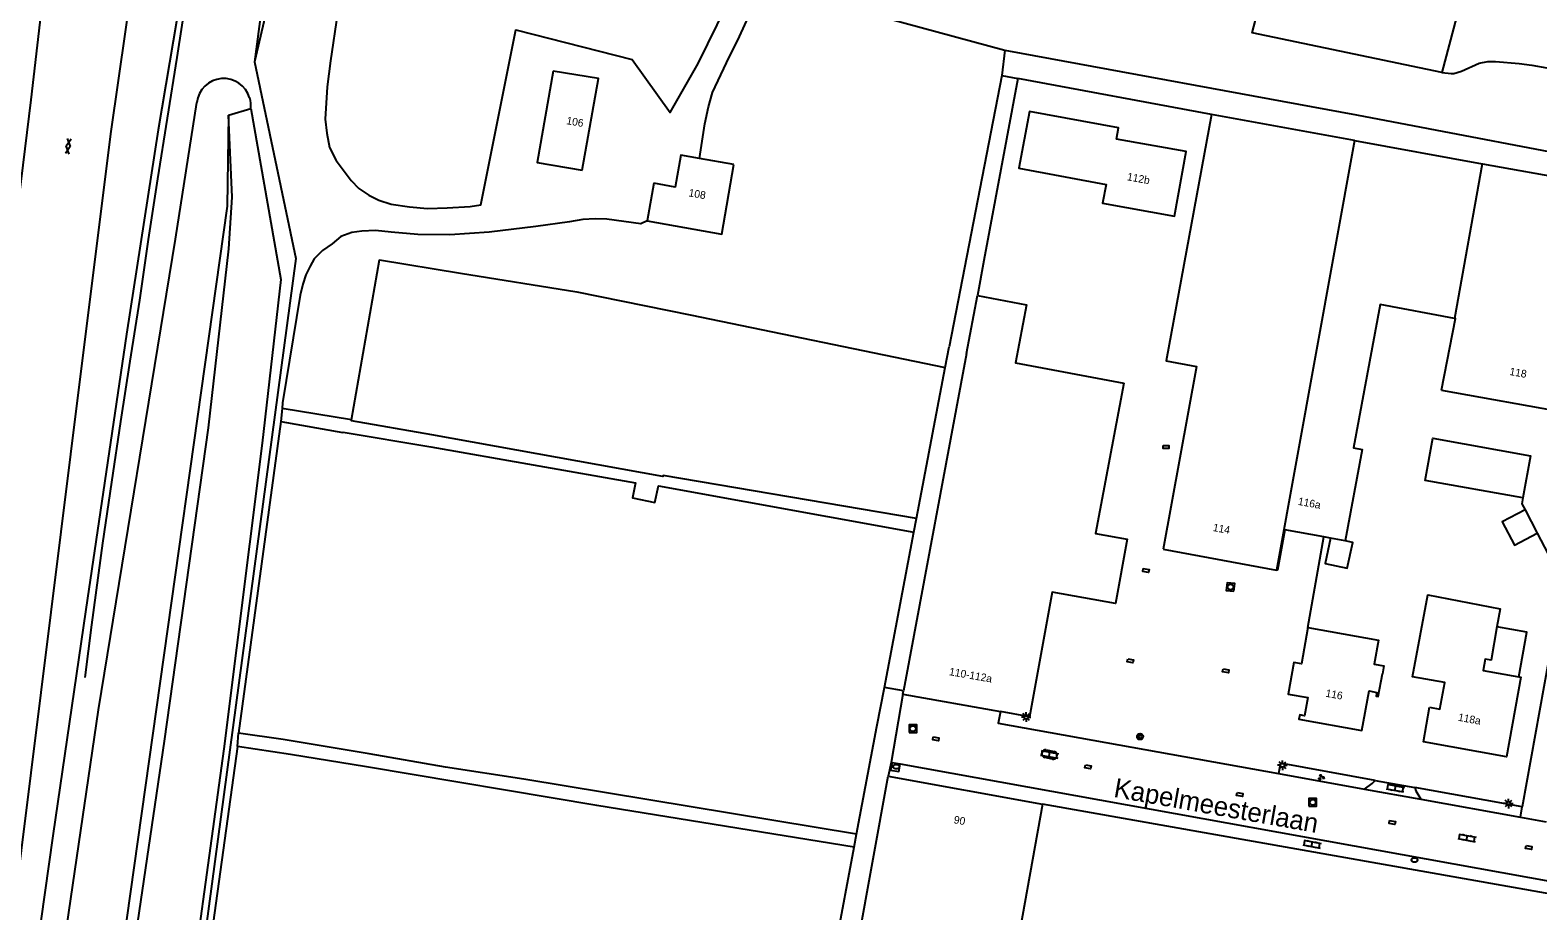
# Model space of a CAD drawing. Extents: x 133000 to 136000, y 400500 to 403500.
# Drawn here: x 133102.6 to 133299.1, y 400603.1 to 400718 of the extents above; entities that cross this region are included whole.
import ezdxf

# ---------------------------------------------------------------- set-up
doc = ezdxf.new("R2010")
doc.units = 0
for name, color, linetype in [('gg-afsc-hekwerk', 7, 'Continuous'), ('gg-afsc-muur', 7, 'Continuous'), ('gg-anno-huisnummerreeks BGT', 7, 'Continuous'), ('gg-anno-openbare ruimte label', 7, 'Continuous'), ('gg-bbg-bijgebouw', 7, 'Continuous'), ('gg-bbg-gedigitaliseerde bebouwing', 7, 'Continuous'), ('gg-bbg-hoofdgebouw', 7, 'Continuous'), ('gg-bbg-luifel en loopbrug', 7, 'Continuous'), ('gg-bbg-tussenscheiding', 7, 'Continuous'), ('gg-knt-BGT kruinlijn', 7, 'Continuous'), ('gg-knt-bovenkant onderkant talud', 7, 'Continuous'), ('gg-knt-verharding', 7, 'Continuous'), ('gt-grn-groengrens', 7, 'Continuous'), ('gt-grn-weggrens', 7, 'Continuous'), ('gt-knt-geleideconstructie', 7, 'Continuous'), ('gt-symb-boom', 7, 'Continuous'), ('gt-symb-brandkraan', 7, 'Continuous'), ('gt-symb-gesloten verharding', 7, 'Continuous'), ('gt-symb-groenvak', 7, 'Continuous'), ('gt-symb-klinker verharding', 7, 'Continuous'), ('gt-symb-kolk center center', 7, 'Continuous'), ('gt-symb-lichtmast', 7, 'Continuous'), ('gt-symb-rioolschacht', 7, 'Continuous')]:
    doc.layers.add(name, color=color, linetype=linetype)

# ---------------------------------------------------------------- blocks, each defined once
blk = doc.blocks.new('gt0-KL1')
at = {"layer": 'gt-symb-klinker verharding'}
for p, q in [((-1.15, 0.3), (1.15, 0.3)), ((-1, -0.3), (-1, 0.3)), ((-0.5, 0.3), (-0.5, 0.45)), ((0, -0.3), (0, 0.3)), ((0.5, 0.3), (0.5, 0.45)), ((1, -0.3), (1, 0.3)), ((-1.15, -0.3), (1.15, -0.3)), ((-0.5, -0.45), (-0.5, -0.3)), ((0.5, -0.45), (0.5, -0.3))]:
    blk.add_line(p, q, dxfattribs=at)
blk = doc.blocks.new('gt0-KOLKCC')
at = {"layer": 'gt-symb-kolk center center'}
blk.add_lwpolyline([(-0.38, 0.2), (0.38, 0.2), (0.38, -0.2), (-0.38, -0.2)], close=True, dxfattribs=at)
blk = doc.blocks.new('gt0-BOOM')
at = {"layer": 'gt-symb-boom'}
for radius in [0.4, 0.2]:
    blk.add_circle((0, 0), radius, dxfattribs=at)
blk = doc.blocks.new('gt0-RS')
at = {"layer": 'gt-symb-rioolschacht'}
blk.add_lwpolyline([(-0.5, -0.5), (0.5, -0.5), (0.5, 0.5), (-0.5, 0.5)], close=True, dxfattribs=at)
blk.add_circle((0, 0), 0.375, dxfattribs=at)
blk = doc.blocks.new('gt0-LMAST')
at = {"layer": 'gt-symb-lichtmast'}
for p, q in [((-0.18, 0.17), (-0.45, 0.44)), ((-0.01, 0.25), (-0.01, 0.62)), ((0.17, 0.17), (0.44, 0.44)), ((-0.26, 0), (-0.63, 0)), ((-0.18, -0.18), (-0.45, -0.45)), ((-0.01, -0.25), (-0.01, -0.63)), ((0.44, -0.45), (0.17, -0.18)), ((0.24, 0), (0.62, 0))]:
    blk.add_line(p, q, dxfattribs=at)
blk.add_circle((-0.01, 0), 0.25, dxfattribs=at)
blk = doc.blocks.new('gt0-GRVAK')
at = {"layer": 'gt-symb-groenvak'}
for p, q in [((-0.11, 0.19), (-0.23, 0.24)), ((-0.18, 0.15), (0.09, 0.15)), ((-0.09, 0.21), (-0.16, 0.32)), ((-0.05, 0.21), (-0.05, 0.39)), ((0, 0.21), (0.06, 0.32)), ((0.01, 0.19), (0.13, 0.24)), ((0.26, -0.05), (0.2, 0.06)), ((0.3, -0.05), (0.3, 0.13)), ((0.35, -0.05), (0.41, 0.06)), ((-0.25, -0.23), (-0.36, -0.18)), ((-0.32, -0.26), (-0.05, -0.26)), ((-0.23, -0.21), (-0.29, -0.1)), ((-0.18, -0.2), (-0.18, -0.02)), ((-0.14, -0.21), (-0.07, -0.1)), ((-0.12, -0.23), (0, -0.18)), ((0.24, -0.07), (0.12, -0.02)), ((0.17, -0.11), (0.44, -0.11)), ((0.37, -0.07), (0.49, -0.02))]:
    blk.add_line(p, q, dxfattribs=at)
blk = doc.blocks.new('gt0-BR')
at = {"layer": 'gt-symb-brandkraan'}
for centre, radius, start, end in [((-0.24, 0), 0.206, 107.5669, 252.4331), ((0.6, -2.66), 3, 106.892, 107.5669), ((0, -0.69), 0.938, 73.108, 106.892), ((-0.6, -2.66), 3, 72.4331, 73.108), ((0.24, 0), 0.206, 287.567, 72.4331), ((0.6, 2.66), 3, 252.4331, 253.108), ((0, 0.69), 0.938, 253.108, 286.8921), ((-0.6, 2.66), 3, 286.8921, 287.567)]:
    blk.add_arc(centre, radius, start, end, dxfattribs=at)
blk = doc.blocks.new('gt0-GESVH1')
at = {"layer": 'gt-symb-gesloten verharding'}
for p, q in [((-0.99, -0.26), (0.01, 0.24)), ((0.01, -0.26), (-0.99, 0.24)), ((0.01, 0.24), (1.01, -0.26)), ((1.01, 0.24), (0.01, -0.26))]:
    blk.add_line(p, q, dxfattribs=at)

msp = doc.modelspace()

# ---------------------------------------------------------------- linework, layer by layer
at = {"layer": 'gg-afsc-hekwerk'}
for p, q in [((133146.76, 400776.86), (133131.81, 400713.84)), ((133221.87, 400673.98), (133222.38, 400676.65)), ((133218.12, 400654.29), (133221.87, 400673.98)), ((133217.79, 400652.52), (133218.12, 400654.29)), ((133213.93, 400632.26), (133217.79, 400652.52)), ((133216.44, 400631.81), (133213.93, 400632.26)), ((133300.85, 400605.32), (133234.55, 400617.03)), ((133210.01, 400611.44), (133210.32, 400613.12)), ((133202.57, 400571.84), (133210.01, 400611.44))]:
    msp.add_line(p, q, dxfattribs=at)
for points in [[(133131.81, 400713.84), (133137.21, 400688.2), (133123.12, 400583.37), (133125.66, 400582.97), (133122.3, 400561.95)], [(133144.49, 400667.14), (133148.14, 400688.01), (133158.66, 400686.29), (133173.86, 400683.84), (133188.64, 400680.83), (133221.87, 400673.98)], [(133210.32, 400613.12), (133212.96, 400627.16), (133213.93, 400632.26)]]:
    msp.add_lwpolyline(points, dxfattribs=at)
at = {"layer": 'gg-afsc-muur'}
for p, q in [((133269.15, 400640.08), (133271.22, 400651.89)), ((133299.05, 400652.37), (133302.37, 400646.01)), ((133301.6, 400641.73), (133297.08, 400616.68)), ((133277.9, 400620.14), (133265.56, 400622.4)), ((133297.08, 400616.68), (133283.08, 400619.22))]:
    msp.add_line(p, q, dxfattribs=at)
msp.add_lwpolyline([(133297.17, 400656.98), (133297.05, 400656.2), (133297.46, 400655.42)], dxfattribs=at)
at = {"layer": 'gg-bbg-bijgebouw'}
for p, q in [((133275.24, 400703.56), (133291.86, 400700.54)), ((133272.09, 400651.73), (133271.22, 400651.89)), ((133274, 400651.37), (133272.09, 400651.73))]:
    msp.add_line(p, q, dxfattribs=at)
for points in [[(133288.25, 400680.38), (133278.56, 400682.17), (133275.1, 400663.49), (133276.21, 400663.28), (133274, 400651.37)], [(133297.17, 400656.98), (133284.45, 400659.25), (133285.43, 400664.75), (133298.15, 400662.48), (133297.17, 400656.98)], [(133271.22, 400651.89), (133266.14, 400652.83), (133265.16, 400647.55), (133265.04, 400647.57)]]:
    msp.add_lwpolyline(points, dxfattribs=at)
at = {"layer": 'gg-bbg-gedigitaliseerde bebouwing'}
for p, q in [((133183.9, 400698), (133183.03, 400693.08)), ((133224.64, 400675.79), (133226.06, 400683.35)), ((133224.64, 400675.79), (133216.44, 400631.81))]:
    msp.add_line(p, q, dxfattribs=at)
for points in [[(133170.75, 400712.63), (133168.69, 400700.72), (133174.55, 400699.69)], [(133183.03, 400693.08), (133192.73, 400691.37), (133194.33, 400700.43)], [(133226.06, 400683.35), (133232.46, 400682.15), (133231.04, 400674.59), (133245.15, 400671.94)]]:
    msp.add_lwpolyline(points, dxfattribs=at)
at = {"layer": 'gg-bbg-hoofdgebouw'}
for p, q in [((133275.24, 400703.56), (133256.56, 400706.96)), ((133194.33, 400700.43), (133189.82, 400701.22)), ((133291.86, 400700.54), (133291.92, 400700.53)), ((133291.92, 400700.53), (133311.63, 400696.97)), ((133250.28, 400650.3), (133265.04, 400647.57)), ((133216.36, 400631.39), (133216.44, 400631.81)), ((133216.36, 400631.39), (133229.06, 400629.13)), ((133201.14, 400547.06), (133214.42, 400620.69)), ((133214.42, 400620.69), (133234.55, 400617.03)), ((133234.55, 400617.03), (133226.33, 400571.6))]:
    msp.add_line(p, q, dxfattribs=at)
for points in [[(133174.55, 400699.69), (133176.66, 400711.64), (133170.75, 400712.63)], [(133244.18, 400703.76), (133244.46, 400705.21), (133232.84, 400707.33), (133231.46, 400699.95), (133242.84, 400697.85), (133242.39, 400695.42), (133251.74, 400693.7), (133253.29, 400702.12), (133244.18, 400703.76)], [(133256.56, 400706.96), (133250.67, 400674.83), (133254.63, 400674.11), (133250.28, 400650.3)], [(133189.82, 400701.22), (133187.39, 400701.65), (133186.65, 400697.47), (133183.9, 400698)], [(133286.58, 400671.04), (133303.01, 400668.08), (133301.8, 400661.83), (133305.04, 400661.25), (133310.46, 400690.77)], [(133286.58, 400671.04), (133288.37, 400680.35), (133288.25, 400680.38)], [(133245.15, 400671.94), (133241.47, 400652.34), (133245.6, 400651.59), (133244.07, 400643.22), (133235.82, 400644.7), (133232.87, 400628.45), (133229.06, 400629.13)], [(133285, 400629.69), (133286.35, 400629.45), (133286.99, 400632.89), (133282.79, 400633.66), (133284.76, 400644.34), (133294.21, 400642.53), (133293.79, 400640.15)], [(133269.15, 400640.08), (133268.32, 400635.34), (133267.32, 400635.52), (133266.59, 400631.39), (133269.14, 400630.94), (133268.71, 400628.57), (133268.08, 400628.69), (133267.98, 400628.14), (133276.16, 400626.63), (133277.11, 400631.81), (133278.15, 400631.62), (133278.05, 400631.12), (133278.32, 400631.07), (133278.86, 400634.02)], [(133269.15, 400640.08), (133278.34, 400638.43), (133277.77, 400635.32), (133279.05, 400635.08), (133278.86, 400634.02)], [(133293.79, 400640.15), (133293.03, 400635.8), (133292.25, 400635.94), (133291.99, 400634.49), (133296.64, 400633.65)], [(133296.64, 400633.65), (133296.92, 400633.6), (133295.03, 400623.21), (133284.21, 400625.19), (133285, 400629.69)]]:
    msp.add_lwpolyline(points, dxfattribs=at)
at = {"layer": 'gg-bbg-luifel en loopbrug'}
msp.add_line((133297.46, 400655.42), (133299.05, 400652.37), dxfattribs=at)
for points in [[(133297.46, 400655.42), (133294.48, 400653.87), (133296.07, 400650.82), (133299.05, 400652.37)], [(133272.09, 400651.73), (133271.38, 400648.43), (133274.27, 400647.8), (133275, 400651.16), (133274, 400651.37)], [(133296.64, 400633.65), (133297.68, 400639.45), (133293.79, 400640.15)]]:
    msp.add_lwpolyline(points, dxfattribs=at)
at = {"layer": 'gg-bbg-tussenscheiding'}
for p, q in [((133275.24, 400703.56), (133265.04, 400647.57)), ((133291.86, 400700.54), (133288.25, 400680.38))]:
    msp.add_line(p, q, dxfattribs=at)
at = {"layer": 'gg-knt-BGT kruinlijn'}
for points in [[(133128.42, 400706.88), (133128.27, 400694.99), (133105.93, 400536.64)], [(133111.16, 400564.01), (133113.74, 400582.18), (133120.11, 400625.28), (133125.83, 400666.1), (133128.49, 400689.46), (133128.92, 400696.19), (133128.42, 400706.88)]]:
    msp.add_lwpolyline(points, dxfattribs=at)
at = {"layer": 'gg-knt-bovenkant onderkant talud'}
for points in [[(133092.5, 400500), (133094.21, 400511.99), (133104.27, 400580.08), (133111.49, 400629.35), (133121.54, 400690.7), (133124.31, 400708.54)], [(133131.33, 400707.76), (133135.26, 400685.46), (133132.83, 400664.1), (133127.84, 400624.24), (133122.24, 400583.48), (133123.68, 400580.79), (133120.9, 400562.21)]]:
    msp.add_lwpolyline(points, dxfattribs=at)
for centre, start, end in [((133127.81, 400708.12), 16.5098, 173.1), ((133127.82, 400708.12), 354.2605, 16.5244)]:
    msp.add_arc(centre, 3.53, start, end, dxfattribs=at)
at = {"layer": 'gg-knt-verharding'}
for p, q in [((133216.36, 400631.39), (133214.82, 400622.5)), ((133235.05, 400624.11), (133236.02, 400623.93)), ((133214.82, 400622.5), (133214.94, 400622.48)), ((133214.94, 400622.48), (133215.98, 400622.29)), ((133215.98, 400622.29), (133301.14, 400606.92)), ((133235.84, 400622.93), (133234.86, 400623.12)), ((133265.32, 400621.03), (133276.53, 400619)), ((133277.9, 400620.14), (133283.08, 400619.22)), ((133276.53, 400619), (133283.86, 400617.68)), ((133283.86, 400617.68), (133296.86, 400615.34)), ((133296.86, 400615.34), (133300.21, 400614.73))]:
    msp.add_line(p, q, dxfattribs=at)
for points in [[(133078.61, 400527.59), (133083.2, 400559.78), (133086.66, 400584.53), (133090.84, 400615.37), (133094.84, 400646.04), (133099.06, 400679.08), (133102.7, 400708.88), (133106.23, 400739.3), (133111.82, 400788.98), (133115.03, 400819.27)], [(133135.16, 400781.78), (133131.12, 400767.61), (133128.6, 400756.55), (133126.23, 400745.68), (133124.65, 400736.87), (133119.25, 400704.94), (133115.15, 400678.34), (133109.82, 400642.41), (133105.53, 400612.9), (133101.83, 400586.77)], [(133229.06, 400629.13), (133228.79, 400627.62), (133265.32, 400621.03)], [(133214.94, 400622.48), (133214.73, 400621.47), (133215.83, 400621.3), (133215.98, 400622.29)], [(133276.53, 400619), (133277.52, 400619.72), (133277.9, 400620.14)], [(133283.08, 400619.22), (133283.21, 400618.77), (133283.86, 400617.68)]]:
    msp.add_lwpolyline(points, dxfattribs=at)
for centre, start, end in [((133234.95, 400623.62), 79.457, 259.3246), ((133235.94, 400623.43), 259.1036, 80.1243)]:
    msp.add_arc(centre, 0.505, start, end, dxfattribs=at)
at = {"layer": 'gt-grn-groengrens'}
for p, q in [((133140.73, 400781.05), (133131.81, 400713.84)), ((133198, 400723.95), (133229.65, 400715.33)), ((133229.65, 400715.33), (133229.26, 400712.03)), ((133229.26, 400712.03), (133222.36, 400676.66)), ((133229.26, 400712.03), (133231.33, 400711.64)), ((133256.56, 400706.96), (133231.33, 400711.64)), ((133128.42, 400706.88), (133131.33, 400707.76)), ((133222.38, 400676.65), (133222.36, 400676.66)), ((133135.45, 400668.61), (133135.28, 400666.93)), ((133144.49, 400667.14), (133135.45, 400668.61)), ((133135.28, 400666.93), (133129.74, 400626.31)), ((133129.62, 400624.58), (133129.74, 400626.31)), ((133265.56, 400622.4), (133265.32, 400621.03)), ((133296.86, 400615.34), (133297.08, 400616.68))]:
    msp.add_line(p, q, dxfattribs=at)
for points in [[(133295.84, 400753.81), (133291.77, 400752.64), (133291.67, 400750.2), (133296.32, 400749.21), (133286.6, 400712.43)], [(133189.82, 400701.22), (133190.54, 400705.73), (133191.03, 400707.95), (133191.55, 400709.81), (133193.36, 400713.71), (133195.04, 400717.12), (133196.46, 400720.19), (133198, 400723.95)], [(133286.6, 400712.43), (133261.89, 400717.61), (133263.25, 400722.96)], [(133142.65, 400720.13), (133141.74, 400713.96), (133141.3, 400710.55), (133141.02, 400706.34), (133141.24, 400704.54), (133141.61, 400702.64), (133142.48, 400700.96), (133144.41, 400698.34), (133145.41, 400697.31), (133146.71, 400696.46), (133148.03, 400695.8), (133149.65, 400695.29), (133152.02, 400694.94), (133154.39, 400694.69), (133156.93, 400694.78), (133159.92, 400694.95), (133161.31, 400695.19), (133165.91, 400718.01), (133181.05, 400714.14), (133186.03, 400707.22), (133189.68, 400713.62), (133193.38, 400721.22)], [(133229.65, 400715.33), (133275.5, 400706.93), (133311.92, 400699.96)], [(133286.6, 400712.43), (133287.84, 400712.3), (133288.18, 400712.32), (133289.15, 400712.59), (133291.46, 400713.67), (133292.6, 400713.89), (133293.61, 400713.88), (133296.68, 400713.6), (133298.35, 400713.39), (133300.31, 400713.06), (133303.04, 400712.45), (133306.9, 400711.4), (133309.87, 400710.75)], [(133231.33, 400711.64), (133226.9, 400687.92), (133226.06, 400683.35)], [(133183.03, 400693.08), (133182.18, 400692.72), (133177.74, 400693.31), (133176.25, 400693.37), (133174.61, 400693.29), (133172.9, 400692.96), (133168.5, 400692.36), (133162.41, 400691.62), (133157.28, 400691.29), (133153.11, 400691.32), (133149.64, 400691.61), (133147.61, 400691.85), (133145.82, 400691.77), (133144.52, 400691.58), (133143.06, 400691.05), (133141.97, 400690.1), (133140.69, 400689.21), (133139.61, 400688.16), (133139.07, 400687.19), (133138.52, 400686.07), (133138.12, 400684.84), (133137.77, 400683.42), (133135.48, 400669.35), (133135.45, 400668.61)], [(133135.28, 400666.93), (133143.36, 400665.49), (133143.37, 400665.54), (133154.81, 400663.62), (133181.5, 400658.92), (133181.12, 400656.99), (133184.03, 400656.37), (133184.48, 400658.54), (133217.79, 400652.52)], [(133218.12, 400654.29), (133185.09, 400659.9), (133185.05, 400659.76), (133154.93, 400665.18), (133144.48, 400667.03), (133144.49, 400667.14)], [(133210.32, 400613.12), (133166.92, 400620.29), (133156.74, 400621.89), (133146.76, 400623.59), (133135.57, 400625.47), (133129.74, 400626.31)], [(133129.62, 400624.58), (133125.47, 400594.69), (133124.36, 400584.85)], [(133210.01, 400611.44), (133176.45, 400616.89), (133146.44, 400621.91), (133136.52, 400623.52), (133129.62, 400624.58)]]:
    msp.add_lwpolyline(points, dxfattribs=at)
at = {"layer": 'gt-grn-weggrens'}
msp.add_line((133214.82, 400622.5), (133214.42, 400620.69), dxfattribs=at)
msp.add_lwpolyline([(133119.87, 400751.96), (133113.09, 400704.74), (133109.13, 400673.17), (133094.9, 400558.97)], dxfattribs=at)
at = {"layer": 'gt-knt-geleideconstructie'}
msp.add_lwpolyline([(133109.74, 400633.56), (133110.63, 400640.42), (133112.07, 400651.07), (133113.21, 400659.02), (133114.41, 400666.92), (133115.61, 400674.82), (133116.86, 400682.75), (133118.01, 400690.65), (133119.22, 400698.58), (133120.48, 400706.49), (133121.73, 400714.4), (133122.98, 400722.3)], dxfattribs=at)

# ---------------------------------------------------------------- block references
at = {"layer": 'gt-symb-boom'}
msp.add_blockref('gt0-BOOM', (133247.27, 400625.86), dxfattribs=at)
at = {"layer": 'gt-symb-brandkraan'}
for p in [(133215.48, 400621.94), (133283.04, 400609.77)]:
    msp.add_blockref('gt0-BR', p, dxfattribs=at)
at = {"layer": 'gt-symb-gesloten verharding', "rotation": 82.8749836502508}
msp.add_blockref('gt0-GESVH1', (133107.53, 400702.82), dxfattribs=at)
at = {"layer": 'gt-symb-groenvak'}
msp.add_blockref('gt0-GRVAK', (133270.86, 400620.56), dxfattribs=at)
at = {"layer": 'gt-symb-klinker verharding'}
for p, rotation in [((133235.46, 400623.54), -10.54573436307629), ((133280.55, 400619.14), -10.545734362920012), ((133269.68, 400611.83), -10.54573436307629), ((133289.88, 400612.65), -10.25359802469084)]:
    msp.add_blockref('gt0-KL1', p, dxfattribs=dict(at, rotation=rotation))
at = {"layer": 'gt-symb-kolk center center'}
msp.add_blockref('gt0-KOLKCC', (133250.65, 400663.61), dxfattribs=at)
for p, rotation in [((133248.03, 400647.52), -10.25359802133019), ((133245.99, 400635.75), -10.253598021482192), ((133258.44, 400634.43), -10.253598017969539), ((133220.64, 400625.55), -10.25359802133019), ((133240.48, 400621.92), -10.25359802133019), ((133260.26, 400618.3), -10.25359802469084), ((133280.14, 400614.67), -10.25359802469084), ((133297.94, 400611.38), -10.25359802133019)]:
    msp.add_blockref('gt0-KOLKCC', p, dxfattribs=dict(at, rotation=rotation))
at = {"layer": 'gt-symb-lichtmast'}
for p in [(133232.42, 400628.41), (133265.83, 400622.12), (133295.29, 400617.13)]:
    msp.add_blockref('gt0-LMAST', p, dxfattribs=at)
at = {"layer": 'gt-symb-rioolschacht', "rotation": 83.28012011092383}
msp.add_blockref('gt0-RS', (133259.05, 400645.36), dxfattribs=at)
at = {"layer": 'gt-symb-rioolschacht'}
for p in [(133217.65, 400626.9), (133269.78, 400617.3)]:
    msp.add_blockref('gt0-RS', p, dxfattribs=at)

# ---------------------------------------------------------------- texts
at = {"layer": 'gg-anno-huisnummerreeks BGT'}
for s, rotation, p in [('106', 350.2, (133172.43, 400705.71)), ('112b', 349.6, (133245.51, 400698.4)), ('108', 350.1, (133188.36, 400696.3)), ('118', 349.8, (133295.37, 400673.01)), ('116a', 349.5, (133267.79, 400656.08)), ('114', 349.5, (133256.7, 400652.67)), ('110-112a', 349.9, (133222.32, 400633.88)), ('116', 349.5, (133271.39, 400631.07)), ('118a', 349.6, (133288.66, 400627.93)), ('90', 349.7, (133222.92, 400614.57))]:
    msp.add_text(s, height=1, rotation=rotation, dxfattribs=at).set_placement(p)
at = {"layer": 'gg-anno-openbare ruimte label'}
msp.add_text('Kapelmeesterlaan', height=2.5, rotation=349.9, dxfattribs=at).set_placement((133243.72, 400618.01))

doc.saveas('drawing.dxf')
